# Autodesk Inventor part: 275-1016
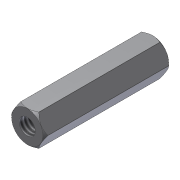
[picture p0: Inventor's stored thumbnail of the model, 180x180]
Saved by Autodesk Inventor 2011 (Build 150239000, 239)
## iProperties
Company: Autodesk Inc.
Created: 2005-07
Part Number: 275-1016
Document SubType Name: Modeling
Designer: Autodesk Inc.
Density: 1 g/cm^3
Catalog Web Link: http://www.vexrobotics.com/products/accessories/structure/standoffs-8-32.html
Description: A standoff is used in mechanics and electronics to separate two parts from one another. All VEX Standoffs have 8-32 threads.
Vendor: Innovation First, Inc.
Author: Autodesk Inc.
Title: VEX Robotics Kit of Parts
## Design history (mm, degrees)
sketch "Sketch1"
  geometry: L1 (1.955, -3.175)-(-1.711, -3.175); L2 (-1.711, -3.175)-(-3.544, 0); L3 (-3.544, 0)-(-1.711, 3.175); L4 (-1.711, 3.175)-(1.955, 3.175); L5 (1.955, 3.175)-(3.788, 0); L6 (3.788, 0)-(1.955, -3.175); 1 further point
  constraints: 12 end point, 1 horizontal, 11 other
  dimensions: "d0" = 6.35 distance between parallel lines of L1 L4
extrude "Extrusion1" new body sketch "Sketch1" distance "d1" = 25.4; taper "d2" = 0 deg
workplane "Work Plane1"
sketch "Sketch3"
  geometry: L1 (-1.325, 0)-(4.974, 0); L2 (5.482, -0.508)-(5.482, -24.892); L3 (4.974, -25.4)-(-1.325, -25.4); L4 (-1.833, -24.892)-(-1.833, -0.508); L5 (-1.833, -0.508)-(-1.325, 0); L6 (4.974, 0)-(5.482, -0.508); L7 (-1.325, -25.4)-(-1.833, -24.892); L8 (5.482, -24.892)-(4.974, -25.4); L9 (-1.833, 0)-(-1.833, -25.4) reference; L10 (3.666, 0)-(5.499, 0) reference; L11 (1.825, 0)-(1.825, -25.4); 4 further points
  constraints: 18 end point, 8 point on line, 2 midpoint, 2 parallel, 1 horizontal, 1 perpendicular
  dimensions: "d5" = 0.508 distance of L4.end point (-1.833, 0); "d6" = 0.508 distance of L1.start point (-1.833, 0) (= d5); "d7" = 0.508 distance of L1.end point (5.482, 0) (= d5); "d8" = 0.508 distance of L2.start point (5.482, 0) (= d7); "d9" = 0.508 distance of L3.end point (-1.833, -25.4) (= d5); "d10" = 0.508 distance of L4.start point (-1.833, -25.4) (= d9); "d11" = 0.508 distance of L2.end point (5.482, -25.4) (= d5); "d12" = 0.508 distance of L3.start point (5.482, -25.4) (= d11); "d13" = 7.3152 distance between parallel lines of L2 L4; "d14" = 0 distance between parallel lines of L9 L4; "d15" = 25.4 distance between parallel lines of L1 L3; "d16" = 0 distance between parallel lines of L1 L10
revolve "Revolution1" sketch "Sketch3" stored, may be unused: angle "d17" = 90 deg
sketch "Sketch4"
  geometry: C1 r 3.15 at (0, 0); C2 r 3.15 at (0, 0) reference; 1 further point
  constraints: 1 centre point, 1 coincident
hole "Hole1" sketch "Sketch4" at (0, 0) diameter "d18" = 3.302; stored, may be unused: countersink angle "d22" = 82 deg, drill point angle "d24" = 118 deg; dims "d19" = 12.7, "d20" = 9.525, "d21" = 6.35, "d23" = 25.4
body "Solid1"
other parameters: "d4" = -3.175
